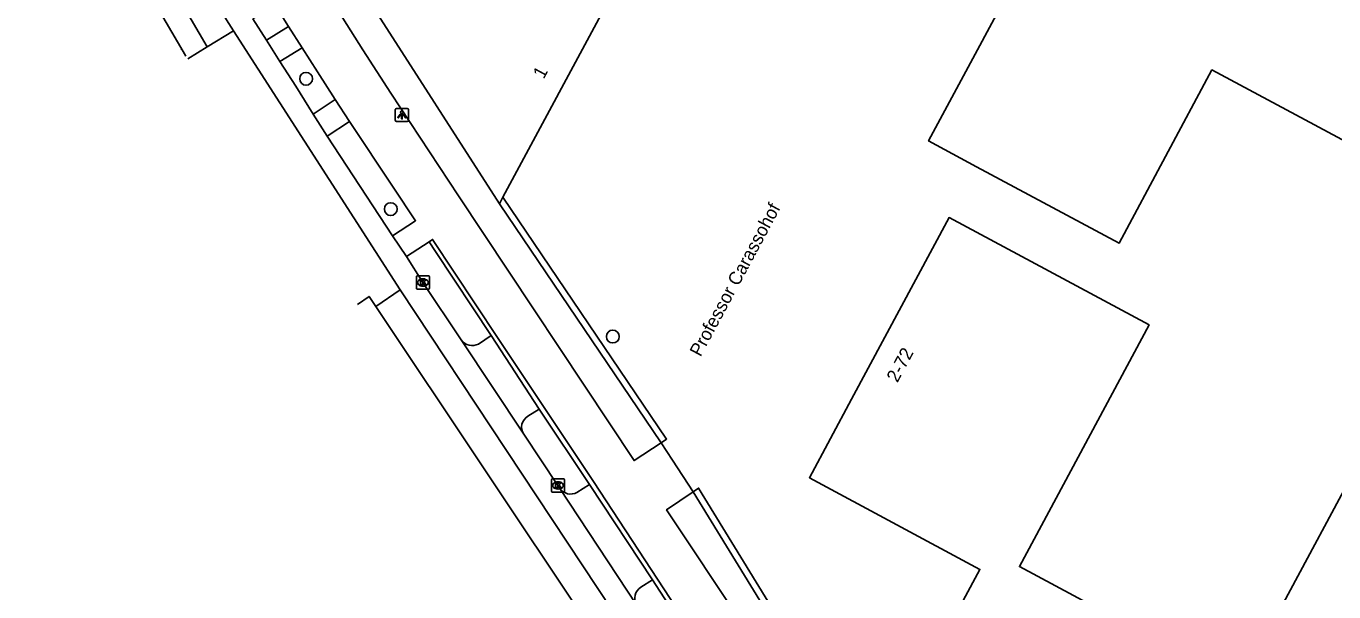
# Model space of a CAD drawing. Extents: x 159489 to 160304, y 383826 to 384530.
# Drawn here: x 159510.2 to 159609.7, y 384218.5 to 384261.6 of the extents above; entities that cross this region are included whole.
import ezdxf

# ---------------------------------------------------------------- set-up
doc = ezdxf.new("R2010")
doc.units = 0
for name, color, linetype in [('IMGEO_Boom', 7, 'Continuous'), ('IMGEO_Groenvoorziening', 7, 'Continuous'), ('IMGEO_Kolk', 7, 'Continuous'), ('IMGEO_Lichtpunt', 7, 'Continuous'), ('IMGEO_Openbare_ruimte_label', 7, 'Continuous'), ('IMGEO_Pand', 7, 'Continuous'), ('IMGEO_Pand_nummerreeks', 7, 'Continuous'), ('IMGEO_Parkeervlak_open', 7, 'Continuous'), ('IMGEO_Rijbaan_lokaal_gesloten', 7, 'Continuous'), ('IMGEO_Rijbaan_lokaal_open', 7, 'Continuous'), ('IMGEO_Voetpad_gesloten', 7, 'Continuous'), ('IMGEO_Voetpad_open', 7, 'Continuous')]:
    doc.layers.add(name, color=color, linetype=linetype)

msp = doc.modelspace()

# ---------------------------------------------------------------- linework, layer by layer
at = {"layer": 'IMGEO_Boom'}
for centre in [(159531.469, 384257.566), (159537.915, 384247.646), (159554.816, 384237.946)]:
    msp.add_circle(centre, 0.489, dxfattribs=at)
at = {"layer": 'IMGEO_Groenvoorziening'}
for points in [[(159546.189, 384248.053), (159558.499, 384229.864)], [(159558.499, 384229.864), (159558.913, 384230.144), (159546.454, 384248.546)], [(159568.737, 384213.4), (159569.144, 384213.675), (159561.341, 384226.407), (159560.934, 384226.137)], [(159568.737, 384213.4), (159560.934, 384226.137)]]:
    msp.add_lwpolyline(points, dxfattribs=at)
at = {"layer": 'IMGEO_Kolk'}
for p, q in [((159539.862, 384241.632), (159539.862, 384242.484)), ((159539.937, 384242.558), (159540.789, 384242.558)), ((159540.35, 384242.338), (159540.375, 384242.338)), ((159540.863, 384242.484), (159540.863, 384241.632)), ((159540.789, 384241.558), (159539.937, 384241.558)), ((159540.373, 384241.778), (159540.348, 384241.778)), ((159550.143, 384226.187), (159550.143, 384227.039)), ((159550.218, 384227.113), (159551.07, 384227.113)), ((159550.654, 384226.333), (159550.629, 384226.333)), ((159550.631, 384226.893), (159550.656, 384226.893)), ((159551.144, 384227.039), (159551.144, 384226.187)), ((159551.07, 384226.113), (159550.218, 384226.113))]:
    msp.add_line(p, q, dxfattribs=at)
for points in [[(159539.862, 384241.632), (159539.862, 384242.484)], [(159539.937, 384242.558), (159540.789, 384242.558)], [(159540.183, 384242.258), (159540.306, 384242.258), (159540.306, 384242.107), (159540.436, 384242.258), (159540.6, 384242.258), (159540.454, 384242.107), (159540.607, 384241.858), (159540.455, 384241.858), (159540.37, 384242.022), (159540.306, 384241.955), (159540.306, 384241.858), (159540.183, 384241.858), (159540.183, 384242.258)], [(159540.863, 384242.484), (159540.863, 384241.632)], [(159540.789, 384241.558), (159539.937, 384241.558)], [(159550.143, 384226.187), (159550.143, 384227.039)], [(159550.218, 384227.113), (159551.07, 384227.113)], [(159550.464, 384226.813), (159550.587, 384226.813), (159550.587, 384226.662), (159550.717, 384226.813), (159550.881, 384226.813), (159550.735, 384226.662), (159550.888, 384226.413), (159550.736, 384226.413), (159550.651, 384226.577), (159550.587, 384226.51), (159550.587, 384226.413), (159550.464, 384226.413), (159550.464, 384226.813)], [(159551.144, 384227.039), (159551.144, 384226.187)], [(159551.07, 384226.113), (159550.218, 384226.113)]]:
    msp.add_lwpolyline(points, dxfattribs=at)
for centre, start, end in [((159539.939, 384242.482), 91.55205, 178.44795), ((159539.939, 384242.482), 91.55205, 178.44795), ((159540.787, 384242.482), 1.55205, 88.44795), ((159540.787, 384242.482), 1.55205, 88.44795), ((159539.939, 384241.634), 181.55205, 268.44795), ((159539.939, 384241.634), 181.55205, 268.44795), ((159540.787, 384241.634), 271.55205, 358.44795), ((159540.787, 384241.634), 271.55205, 358.44795), ((159550.22, 384227.037), 91.55205, 178.44795), ((159550.22, 384227.037), 91.55205, 178.44795), ((159550.22, 384226.189), 181.55205, 268.44795), ((159550.22, 384226.189), 181.55205, 268.44795), ((159551.068, 384227.037), 1.55205, 88.44795), ((159551.068, 384227.037), 1.55205, 88.44795), ((159551.068, 384226.189), 271.55205, 358.44795), ((159551.068, 384226.189), 271.55205, 358.44795)]:
    msp.add_arc(centre, 0.0765, start, end, dxfattribs=at)
for centre, major_axis, ratio, start_param, end_param in [((159540.349, 384242.058), (-0.387, 0.002), 0.722429, 4.712389, 7.853982), ((159540.374, 384242.058), (-0.39, 0.002), 0.717154, 1.570796, 4.712389), ((159550.63, 384226.613), (-0.387, 0.002), 0.722429, 4.712389, 7.853982), ((159550.655, 384226.613), (-0.39, 0.002), 0.717154, 1.570796, 4.712389)]:
    msp.add_ellipse(centre, major_axis=major_axis, ratio=ratio, start_param=start_param, end_param=end_param, dxfattribs=at)
at = {"layer": 'IMGEO_Lichtpunt'}
for p, q in [((159538.262, 384255.219), (159538.262, 384254.412)), ((159538.262, 384255.219), (159538.262, 384254.412)), ((159539.164, 384255.314), (159538.356, 384255.314)), ((159539.164, 384255.314), (159538.356, 384255.314)), ((159539.258, 384254.412), (159539.258, 384255.219)), ((159539.258, 384254.412), (159539.258, 384255.219)), ((159538.356, 384254.318), (159539.164, 384254.318)), ((159538.356, 384254.318), (159539.164, 384254.318))]:
    msp.add_line(p, q, dxfattribs=at)
for points in [[(159538.636, 384254.883), (159538.675, 384254.855), (159538.487, 384254.593), (159538.449, 384254.62), (159538.636, 384254.883)], [(159538.738, 384254.835), (159538.785, 384254.835), (159538.785, 384254.513), (159538.738, 384254.513), (159538.738, 384254.835)], [(159538.848, 384254.855), (159538.886, 384254.882), (159539.073, 384254.62), (159539.034, 384254.592), (159538.848, 384254.855)]]:
    msp.add_lwpolyline(points, dxfattribs=at)
msp.add_circle((159538.761, 384255.017), 0.0994, dxfattribs=at)
for centre, start, end in [((159538.356, 384255.219), 90, 180), ((159538.356, 384255.219), 90, 180), ((159539.164, 384255.219), 0, 90), ((159539.164, 384255.219), 0, 90), ((159538.356, 384254.412), 180, 270), ((159538.356, 384254.412), 180, 270), ((159539.164, 384254.412), 270, 0), ((159539.164, 384254.412), 270, 360)]:
    msp.add_arc(centre, 0.0946, start, end, dxfattribs=at)
at = {"layer": 'IMGEO_Pand'}
for points in [[(159590.223, 384274), (159587.23, 384268.419), (159578.85, 384252.831), (159582.491, 384250.872), (159593.348, 384245.049), (159600.425, 384258.245), (159616.379, 384249.69)], [(159546.454, 384248.546), (159554.827, 384264.14)], [(159536.462, 384263.182), (159546.189, 384248.053)], [(159546.454, 384248.546), (159546.189, 384248.053)], [(159584.34, 384188.267), (159598.102, 384213.824), (159585.772, 384220.436), (159595.639, 384238.832), (159580.412, 384246.999), (159572.996, 384233.183), (159569.777, 384227.198), (159582.76, 384220.223), (159574.428, 384204.726)], [(159627.071, 384201.275), (159618.808, 384205.718), (159623.257, 384213.945), (159629.821, 384226.083), (159614.722, 384234.18), (159602.531, 384211.447), (159601.626, 384209.778), (159609.875, 384205.335), (159596.947, 384181.297), (159611.51, 384173.469)]]:
    msp.add_lwpolyline(points, dxfattribs=at)
at = {"layer": 'IMGEO_Parkeervlak_open'}
for points in [[(159545.553, 384238.015), (159544.603, 384237.375)], [(159549.217, 384232.423), (159548.342, 384231.88)], [(159553.047, 384226.686), (159552.088, 384226.068)], [(159556.941, 384218.865), (159557.829, 384219.423)]]:
    msp.add_lwpolyline(points, dxfattribs=at)
for centre, radius, start, end in [((159544.121, 384238.319), 1.06, 216.00906, 297.04799), ((159548.841, 384231.054), 0.965, 121.15353, 213.21599), ((159551.62, 384227.012), 1.054, 216.71097, 296.39), ((159557.483, 384218.026), 0.999, 122.88057, 210.65261)]:
    msp.add_arc(centre, radius, start, end, dxfattribs=at)
at = {"layer": 'IMGEO_Rijbaan_lokaal_gesloten'}
for points in [[(159510.16, 384283.557), (159523.948, 384259.997)], [(159522.115, 384259.647), (159511.588, 384277.632)], [(159525.931, 384261.215), (159522.428, 384266.788)], [(159527.408, 384262.135), (159528.457, 384260.496)], [(159538.641, 384241.501), (159525.931, 384261.215)], [(159523.948, 384259.997), (159522.463, 384259.078)], [(159528.457, 384260.496), (159529.475, 384258.882)], [(159522.313, 384259.295), (159522.115, 384259.647)], [(159529.475, 384258.882), (159530.676, 384256.993), (159531.995, 384254.871)], [(159531.995, 384254.871), (159533.078, 384253.19)], [(159533.078, 384253.19), (159538.058, 384245.622)], [(159538.058, 384245.622), (159539.105, 384244.038)], [(159539.105, 384244.038), (159540.363, 384242.058), (159543.263, 384237.696)], [(159554.807, 384217.036), (159538.641, 384241.501)], [(159535.383, 384240.391), (159536.266, 384241.006), (159536.788, 384240.242)], [(159536.788, 384240.242), (159553.006, 384215.893)], [(159543.263, 384237.696), (159548.034, 384230.526)], [(159548.034, 384230.526), (159550.644, 384226.613), (159550.775, 384226.382)], [(159550.775, 384226.382), (159556.624, 384217.517)]]:
    msp.add_lwpolyline(points, dxfattribs=at)
at = {"layer": 'IMGEO_Rijbaan_lokaal_open'}
for points in [[(159525.931, 384261.215), (159523.948, 384259.997)], [(159538.641, 384241.501), (159536.788, 384240.242)]]:
    msp.add_lwpolyline(points, dxfattribs=at)
at = {"layer": 'IMGEO_Voetpad_gesloten'}
for points in [[(159540.836, 384245.167), (159541.101, 384245.34), (159546.045, 384237.884), (159553.341, 384226.923), (159558.212, 384219.486), (159567.124, 384205.873), (159570.37, 384200.648), (159573.493, 384195.607), (159576.772, 384190.223), (159580.547, 384183.998), (159583.202, 384179.454), (159586.011, 384174.587), (159589.675, 384168.05), (159594.72, 384159.028), (159592.622, 384157.909)], [(159545.553, 384238.015), (159541.321, 384244.432), (159540.836, 384245.167)], [(159549.217, 384232.423), (159545.553, 384238.015)], [(159553.047, 384226.686), (159549.217, 384232.423)], [(159557.829, 384219.423), (159553.047, 384226.686)], [(159557.829, 384219.423), (159559.903, 384216.259)]]:
    msp.add_lwpolyline(points, dxfattribs=at)
at = {"layer": 'IMGEO_Voetpad_open'}
for points in [[(159534.333, 384266.954), (159532.141, 384265.589), (159535.783, 384259.763), (159537.922, 384256.46), (159543.06, 384248.654), (159556.437, 384228.499), (159558.499, 384229.864)], [(159530.14, 384261.558), (159529.056, 384263.238), (159527.408, 384262.135)], [(159530.14, 384261.558), (159528.457, 384260.496)], [(159531.17, 384259.924), (159530.14, 384261.558)], [(159529.475, 384258.882), (159531.17, 384259.924)], [(159533.67, 384255.984), (159532.339, 384258.083), (159531.17, 384259.924)], [(159531.995, 384254.871), (159533.67, 384255.984)], [(159534.768, 384254.316), (159533.67, 384255.984)], [(159533.078, 384253.19), (159534.768, 384254.316)], [(159538.058, 384245.622), (159539.805, 384246.756), (159538.106, 384249.307), (159534.768, 384254.316)], [(159540.836, 384245.167), (159539.105, 384244.038)], [(159560.934, 384226.137), (159559.363, 384228.538), (159558.499, 384229.864)], [(159560.934, 384226.137), (159558.905, 384224.769), (159564.664, 384216.096), (159567.101, 384212.363), (159568.737, 384213.4)]]:
    msp.add_lwpolyline(points, dxfattribs=at)
msp.add_arc((159521.341, 384259.112), 0.94, 34.65018, 50.89474, dxfattribs=at)

# ---------------------------------------------------------------- texts
at = {"layer": 'IMGEO_Openbare_ruimte_label'}
msp.add_text('Professor Carassohof', height=1, rotation=61.7691, dxfattribs=at).set_placement((159561.491, 384236.351))
at = {"layer": 'IMGEO_Pand_nummerreeks'}
for s, rotation, p in [('1', 61.57004, (159549.558, 384257.501)), ('2-72', 61.76485, (159576.479, 384234.387))]:
    msp.add_text(s, height=1, rotation=rotation, dxfattribs=at).set_placement(p)

doc.saveas('drawing.dxf')
